Omron CX-Programmer project NuevoProyecto (CX-Programmer 9.50)

# PLC NuevoPLC1: CP1L-E EM

## Program P1_5 (cyclic task 0)
Local symbols
B 100.00 BOOL
FSp 15.00 BOOL
p 0.00 BOOL

### Section Sección1_Programa_principal

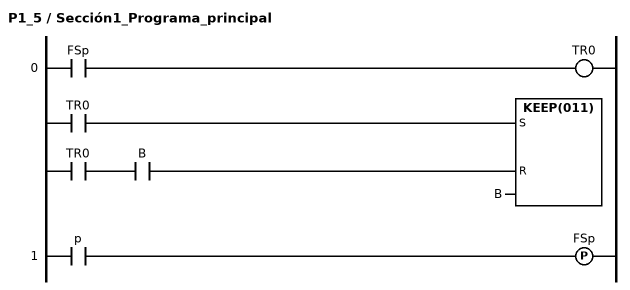
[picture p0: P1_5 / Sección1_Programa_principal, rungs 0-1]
; rung 0
LD FSp
OUT TR0
LD TR0
AND B
KEEP(011) B
; rung 1
LD p
DIFU(013) FSp

### Section END
; rung 0
END(001)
